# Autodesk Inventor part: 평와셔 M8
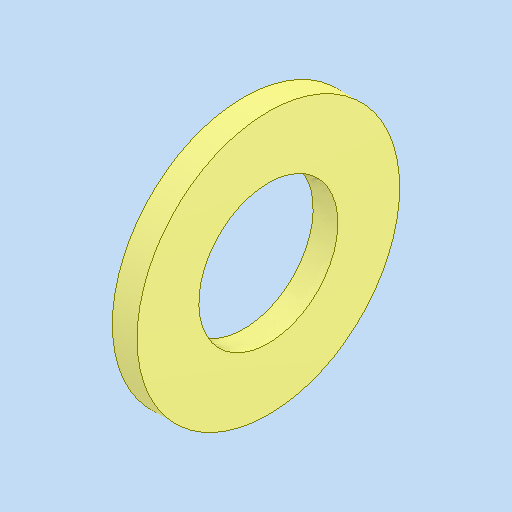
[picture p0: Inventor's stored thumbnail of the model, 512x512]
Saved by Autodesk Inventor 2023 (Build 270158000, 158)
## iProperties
Created: 2024-11
Part Number: 평와셔 M8
Material: 강철, 연강
Description: 평면 와셔
Document SubType Name: Modeling
Designer: asung
Density: 7.85 g/cm^3
Appearance: 기본값
Author: jhkim
Sending System: Autodesk Inventor 2025
Preprocessor: ST-DEVELOPER v20
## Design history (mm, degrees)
feature "Solid1"
node "솔리드1"
